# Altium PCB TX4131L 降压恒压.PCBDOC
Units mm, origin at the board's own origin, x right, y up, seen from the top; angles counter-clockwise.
Board outline 46.75 x 30.25 mm, 2 copper layers (TopLayer, BottomLayer); 29 components, 14 nets, 65 pads, 68 vias.
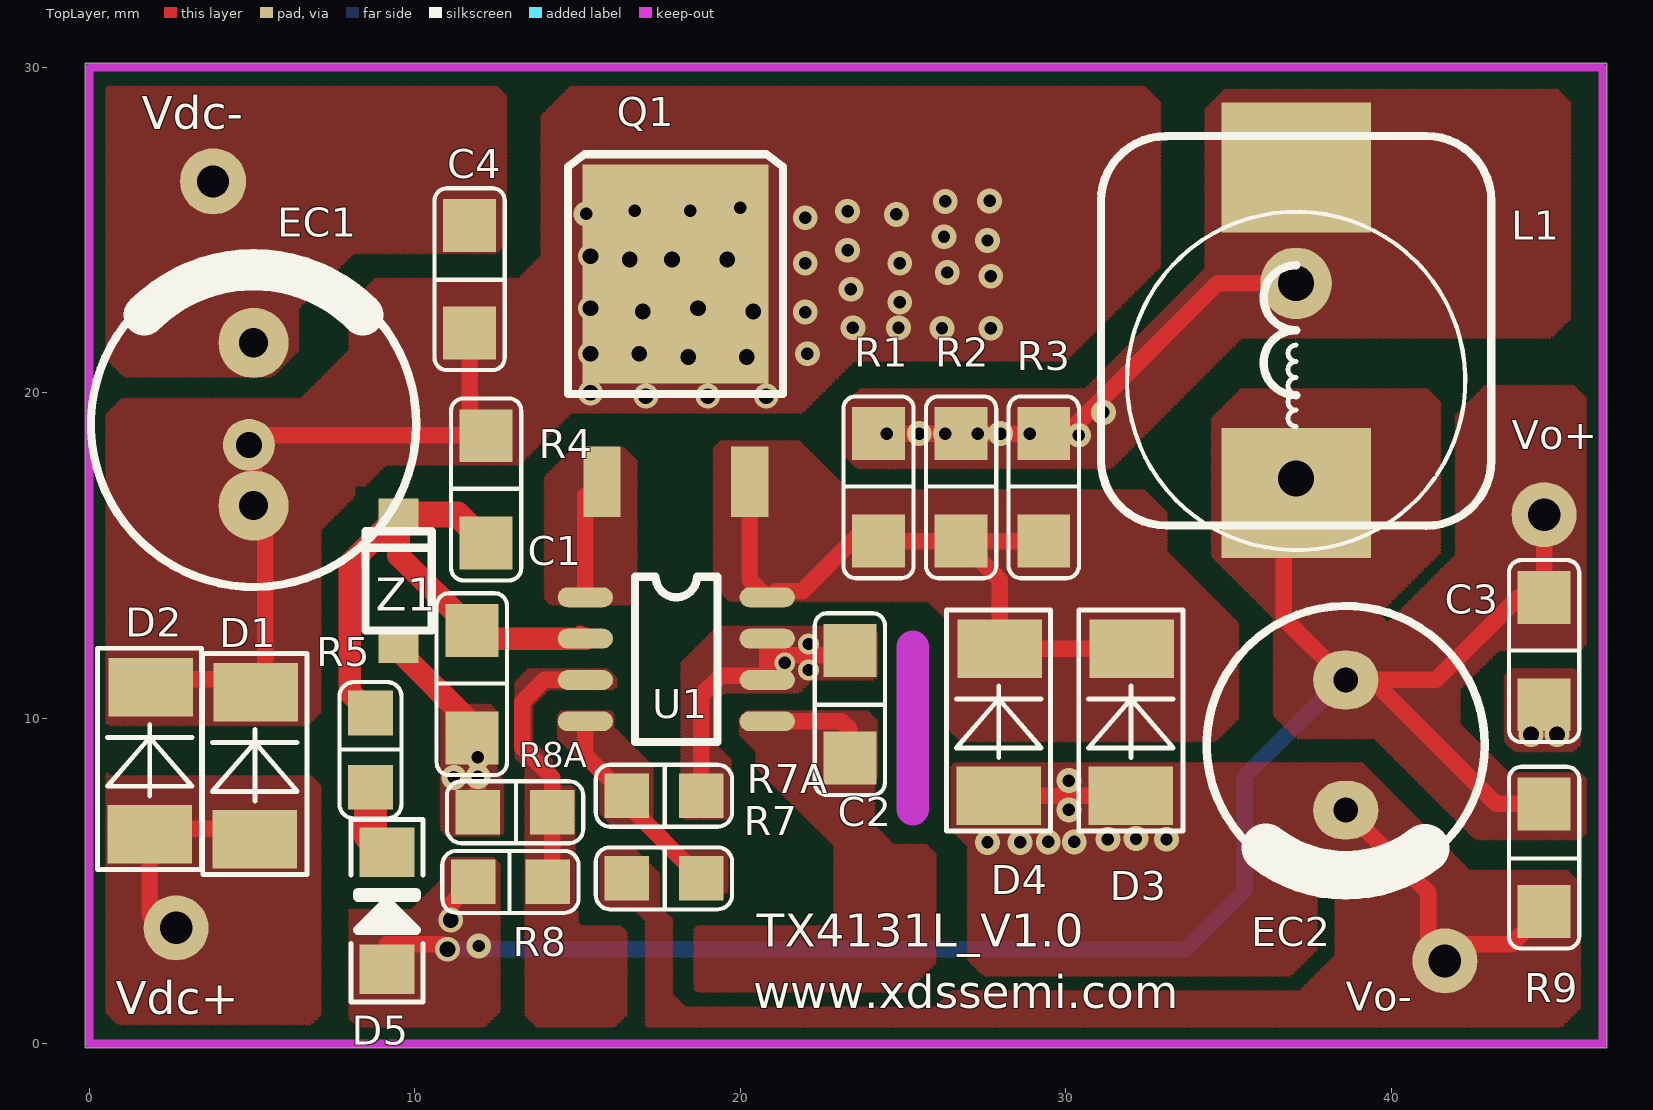
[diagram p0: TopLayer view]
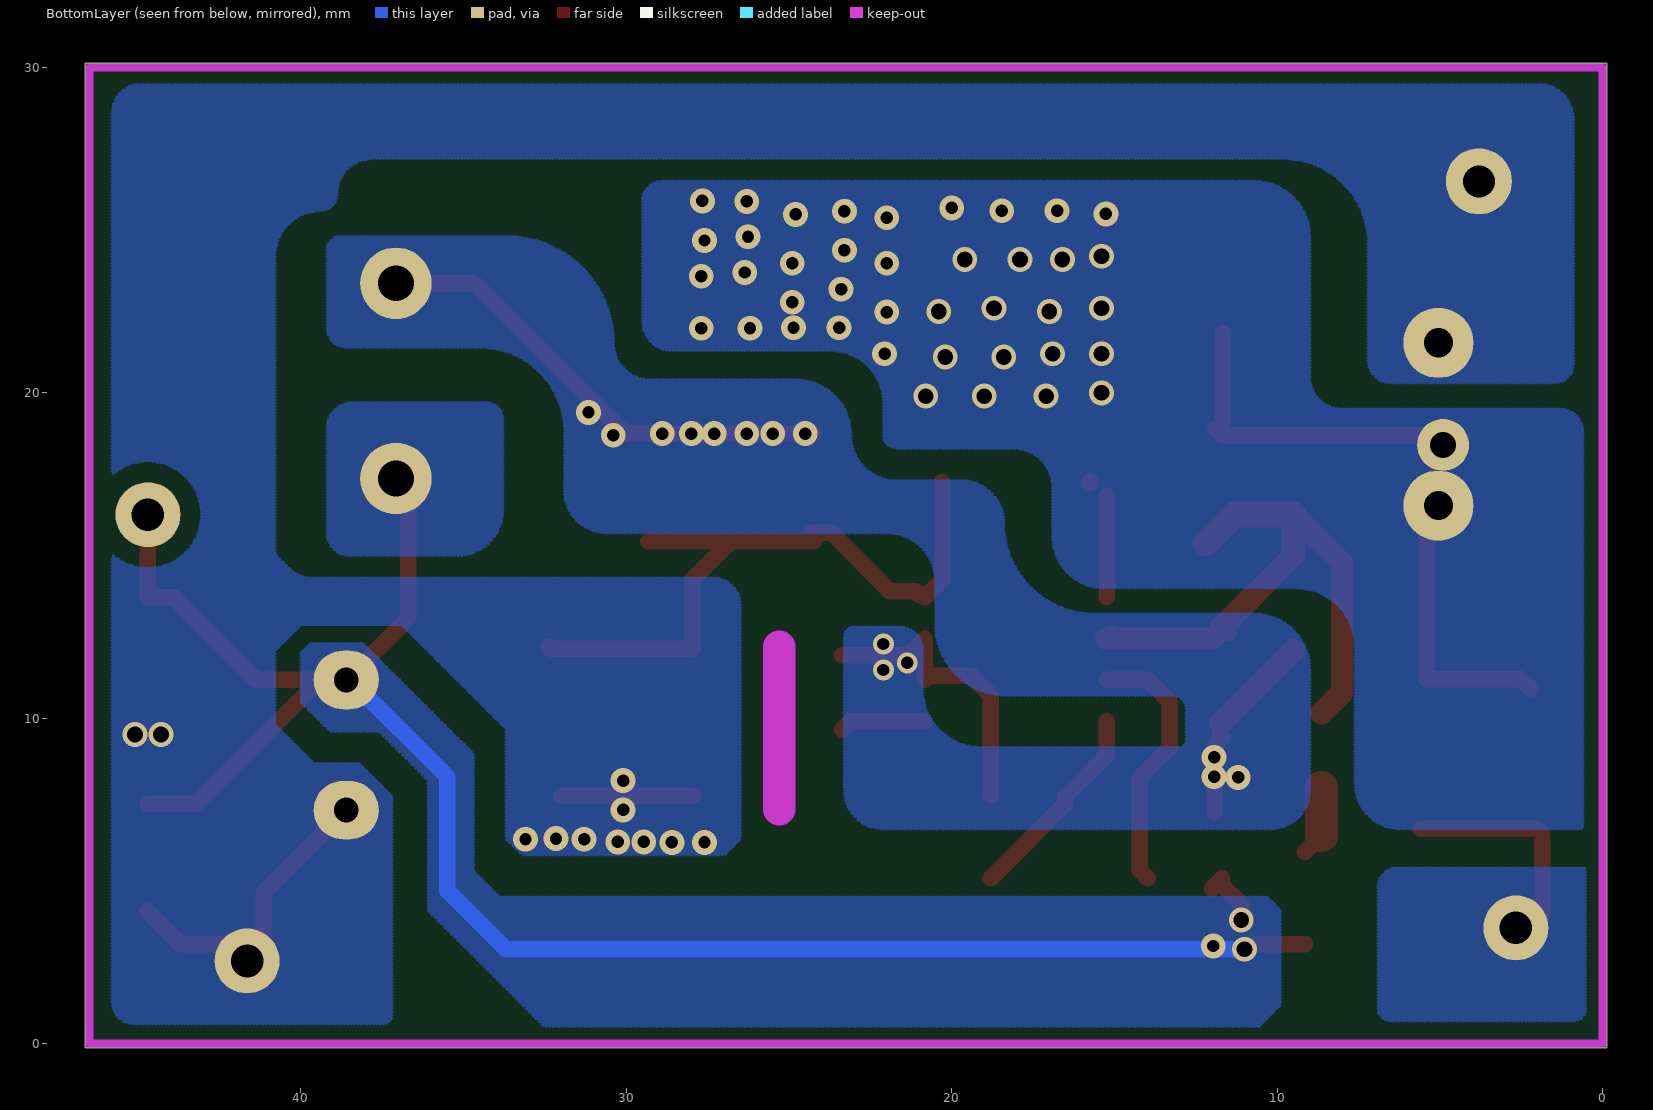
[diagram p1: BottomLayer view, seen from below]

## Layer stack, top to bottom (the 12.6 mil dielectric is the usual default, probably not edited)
TopLayer: signal copper 0.0356
Dielectric: dielectric 0.32, FR-4, Dk 4.8
BottomLayer: signal copper 0.0356

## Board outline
-0.127,-0.127 46.627,-0.127 46.627,30.127 -0.127,30.127

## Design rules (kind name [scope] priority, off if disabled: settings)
Clearance [All] p1: gap=0.35
ComponentClearance [All] p1 off: gap=0.254 collisioncheckmode=3 verticalgap=0.254 showdistances=FALSE
PolygonConnect [All] p1: connectstyle=Direct reliefconductorwidth=0.254 reliefentries=4 polygonreliefangle="90 Angle"
RoutingVias [All] p1: holewidth=0.711 width=1.27 viastyle="Through Hole" minholewidth=0.711 minwidth=1.27 maxholewidth=0.711 maxwidth=1.27
SilkscreenOverComponentPads [All] p1: minsilkscreentomaskgap=0.254
SolderMaskExpansion [All] p1: expansion=0.102
TestPointUsage [All] p1: valid=0 allowmultiple=FALSE
Testpoint [All] p1: side=15 testpointundercomponent=TRUE minsize=1.016 maxsize=2.54 preferedsize=1.524 minholesize=0.508 maxholesize=1.016 preferedholesize=0.813 testpointgrid=0.025 style=1023 order=0123456789
Width [All] p1: maxlimit=0.508 minlimit=0.508 preferedwidth=0.508
22 further rules are at their usual default settings.

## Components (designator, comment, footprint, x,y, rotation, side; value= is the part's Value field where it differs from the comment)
C1 "" R1206 11.75,12.7 r0 top
C2 "" R1206 23.368,8.783 r180 top
C3 "" R1206 44.704,13.716 r0 top
C4 "" R1206 11.684,21.844 r180 top
D1 "" SMB 5.08,6.283 r90 top
D2 "" SMB 1.848,6.44 r90 top
D3 "" SMB 32.004,7.62 r90 top
D4 "" SMB 27.94,7.62 r90 top
D5 "" DZSMA 9.144,2.283 r0 top
EC1 "" c10*16 5.044,16.536 r90 top
EC2 "" C8*12 38.608,11.176 r180 top
L1 "" L12*12 37.084,26.924 r270 top
Q1 "" TO252 15.748,17.272 r0 top
R1 "" R1206 24.248,18.748 r0 top
R2 "" R1206 26.788,18.748 r0 top
R3 "" R1206 29.328,18.748 r0 top
R4 "" R1206 12.192,18.683 r0 top
R5 "" R0805 8.636,10.16 r180 top
R7 "" r0805 18.796,5.08 r90 top
R7A "" r0805 18.796,7.62 r90 top
R8 "" r0805 11.792,4.972 r270 top
R8A "" r0805 14.224,7.112 r90 top
R9 "" R1206 44.704,4.064 r180 top
U1 "TX4131L" SOP8 15.24,13.716 r90 top
Vo+ "" pad 44.704,16.256 r0 top
Vo- "" pad 41.656,2.54 r0 top
Z1 "" SOD123 9.5,12.192 r90 top
? "" pad 2.663,3.556 r0 top
? "" L10*16 37.084,23.368 r270 top

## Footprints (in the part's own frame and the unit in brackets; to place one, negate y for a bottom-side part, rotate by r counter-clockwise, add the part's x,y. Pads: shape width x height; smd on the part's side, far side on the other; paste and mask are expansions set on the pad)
C8*12 [mm]
  oval 2x1.8 hole 0.762: 1(0,0) 2(0,4)
  silkscreen extent -4.27,-2.27 4.27,6.27
c10*16 [mil]
  round 85 hole 35.43: 1(0,0) 2(196.85,0)
  silkscreen extent -98,-197 295,197
DZSMA [mm]
  rect 1.7x1.524 smd: 1(0,0) 2(0,3.6)
  silkscreen extent -1.1,-1.01 1.1,4.6
L10*16 [mm]
  round 2.2 hole 1.1: 1(0,0) 2(6,0)
  silkscreen extent -2.2,-5.2 8.2,5.2
L12*12 [mm]
  rect 4x4.6 smd: 1(0,0) 2(10,0)
  silkscreen extent -0.97,-6 11.01,6
pad [mm]
  round 2 hole 1: 1(0,0)
R0805 [mil]
  rect 54x54 smd: 1(0,0) 2(0,90)
  silkscreen extent -38,-38 38,128
r0805 [mil]
  rect 54x54 smd: 1(0,0) 2(0,90)
  silkscreen extent -38,-38 38,128
R1206 [mil]
  rect 64x64 smd: 1(0,0) 2(0,-130)
  silkscreen extent -42,-175 42,45
SMB [mm]
  rect 1.8x2.6 smd: 1(0,0) 2(4.511,-0.031)
  silkscreen extent -1.09,-1.6 5.71,1.6
SOD123 [mm]
  rect 1x1.22 smd: 1(0,0) 2(4.064,0)
  silkscreen extent 0.51,-1.02 3.56,1.02
SOP8 [mil]
  oval 24x66.93 smd: 1(0,0) 2(-50,0) 3(-100,0) 4(-150,0) 5(-150,-220) 6(-100,-220) 7(-50,-220) 8(0,-220)
  round 27.56 on Top Overlay: ""(-22.13,-84.65)
  silkscreen extent -175,-160 25,-60
TO252 [mil]
  rect 45x85 smd: 1(0,0) 3(179,0)
  rect 225x265 smd: 2(89,251)
  silkscreen extent -41,106 219,396

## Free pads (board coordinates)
  round 2.032 hole 0.991: 0(3.8,26.5)
  round 1.6 hole 0.8: 2(4.9,18.4)

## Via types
v1: diameter 0.762, hole 0.381, TopLayer to BottomLayer, 45 vias
v2: diameter 0.762, hole 0.483, TopLayer to BottomLayer, 20 vias
v3: diameter 0.635, hole 0.381, TopLayer to BottomLayer, 3 vias

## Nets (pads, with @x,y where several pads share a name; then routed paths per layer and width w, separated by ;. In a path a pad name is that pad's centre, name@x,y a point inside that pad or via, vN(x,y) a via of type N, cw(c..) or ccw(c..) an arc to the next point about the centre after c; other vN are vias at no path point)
GND: C3.2 C4.2 D3.1 D4.1 EC1.2 EC2.2 pad.0 R7.2 R9.1 Vo-.1 | length 13.7
  TopLayer w0.508: D4.1 D3.1 ; EC2.2@38.176,7.176 EC2.2 41.148,4.636 41.148,3.048 43.688,3.048 R9.1
  other v1: 27.6,6.183 28.6,6.183 29.463,6.2 30.263,6.2 31.3,6.283 33.1,6.283 32.163,6.3 30.1,7.183 30.1,8.083
  other v2: 44.3,9.5 45.1,9.5
NetC5_1: R7.1 R7A.2 U1.4 | length 6.3
  TopLayer w0.508: U1.4 15.24,8.86 16.495,7.605 16.5,7.6 16.5,7.376 R7.1
NetD1_2: C4.1 D1.2 D2.2 EC1.1 pad.2 Q1.2 R4.1 | length 21.4
  TopLayer w0.508: D2.2@2.2,10.9 2.5,11.2 5.4,11.2 5.4,16.18 EC1.1 5.044,18.356 4.7,18.7 11.7,18.7 R4.1@11.9,18.9 ; R4.1@11.684,18.796 C4.1
  other v1: 22.063,21.2 26.2,21.983 27.7,21.983 23.463,22 24.863,22 22,22.483 24.9,22.783 23.4,23.183 27.7,23.583 26.363,23.7 22,23.983 24.9,23.983 23.3,24.383 27.6,24.683 26.263,24.8 22,25.383 24.8,25.483 15.263,25.5 23.3,25.583 16.763,25.6 18.463,25.6 20,25.683 26.3,25.883 27.663,25.9
  other v2: 17.1,19.9 19,19.9 20.8,19.9 15.4,20 18.4,21.1 20.2,21.1 15.4,21.2 16.9,21.2 17,22.5 20.4,22.5 15.4,22.6 18.7,22.6 16.6,24.1 17.9,24.1 19.6,24.1 15.4,24.2
NetD5_1: ?.2 C3.1 D5.1 EC2.1 L1.2 R8.1 R9.2 Vo+.1 | length 60.6
  TopLayer w0.508: 9.144,3.048 10.852,3.048 v2(11,2.9) ; v2(11.1,3.8) 11.1,4.279 R8.1 ; R8.1@11.684,5.08 R8.1@12,4.764 ; ?.2 36.7,16.984 36.7,13.084 EC2.1 41.376,11.176 43.916,13.716 C3.1 Vo+.1 ; EC2.1@39.424,11.176 43.234,7.366 R9.2
  BottomLayer w0.508: v2(11,2.9) 33.7,2.9 35.5,4.7 35.5,8.2 38.476,11.176 EC2.1
  other v1: 11.963,3
NetQ1_3: D3.2 D4.2 Q1.3 R1.2 R2.2 R3.2 U1.8 | length 21.2
  TopLayer w0.508: Q1.3 20.295,14.249 U1.8 ; U1.8@21,13.8 21.1,13.9 21.9,13.9 23.7,15.7 24.248,15.7 R1.2@24.3,15.7 ; R1.2 R2.2 ; R3.2 R2.2 ; D3.2@32.4,12.2 32.331,12.131 D3.2 D4.2 27.971,14.263 R2.2
NetR4A_1: C1.1 R4.2 R5.1 U1.2 Z1.2 | length 18.6
  TopLayer w0.508: C1.1@11.5,12.6 C1.1@11.6,12.7 ; C1.1@11.684,12.784 11.675,12.775 C1.1@11.6,12.7 ; C1.1 C1.1@11.75,12.75 ; C1.1@11.9,12.4 11.675,12.625 C1.1@11.6,12.7 ; U1.2@15.086,12.6 U1.2
  TopLayer w0.7: R5.1 8,10.796 8,14.756 Z1.2 9.5,15 C1.1@11.75,12.75 ; C1.1@12.054,12.446 U1.2
  TopLayer w0.8: Z1.2 11.317,16.256 R4.2
NetR5_2: D5.2 R5.2 | length 2.2
  TopLayer w0.508: D5.2@8.636,6.391 D5.2
  TopLayer w1: D5.2@8.636,6.391 R5.2
NetR6_1: 
NetR6_2: C2.1 U1.5 | length 2.6
  TopLayer w0.508: U1.5 23.114,9.906 23.368,9.652
NetR8A_1: R8.2 R8A.1 U1.3 | length 8.1
  TopLayer w0.508: R8.2@13.97,5.08 14.224,5.334 R8A.1 14.224,8.176 13.3,9.1 13.3,10.5 13.976,11.176 U1.3
NetU1_1: Q1.1 U1.1 | length 3.2
  TopLayer w0.508: U1.1 Q1.1@15.24,16.84 ; Q1.1@15.748,17.208 Q1.1
NetVAC1_1: 
NetVAC2_1: ?.1@2.663,3.556 D1.1 D2.1 | length 7.4
  TopLayer w0.508: ?.1@2.6,3.2 1.848,3.952 D2.1 2.012,6.604 D1.1@5.588,6.604
SGND: ?.1@37.084,23.368 C1.2 C2.2 L1.1 R1.1 R2.1 R3.1 R7A.1 R8A.2 U1.6 U1.7 Z1.1 | length 30.3
  TopLayer w0.508: Z1.1@9.5,12.083 Z1.1 ; C1.2@11.684,9.398 11.717,9.365 11.938,9.144 v1(11.938,8.8) v1(11.938,8.2) R8A.2 ; C1.2 C1.2@11.75,9.833 ; R7A.1 18.796,10.696 19.4,11.3 20.704,11.3 U1.6 20.828,11.7 U1.7 21.336,11.938 21.363,11.938 22.1,11.938 C2.2@23.368,11.938 ; R1.1 v1(24.5,18.748) v1(25.5,18.748) v1(26.3,18.748) R2.1 v1(27.3,18.748) v1(28,18.748) v1(28.9,18.748) R3.1 30.048,18.748 30.2,18.9 30.931,19.631 34.668,23.368 ?.1@37.084,23.368
  TopLayer w0.7: Z1.1@9.5,12.083 C1.2@11.75,9.833
  other v1: 11.2,8.183 30.4,18.7 31.163,19.4
  other v3: 22.1,11.483 21.363,11.7 22.1,12.283
pads on no net: U1.

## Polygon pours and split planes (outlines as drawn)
GND on TopLayer "TopLayer-GND" (hatched 90Degree grid 0.1 track 0.1, remove dead copper, pour order 1000): 43.5,11.2 43.5,9.3 43.8,9 45.6,9 45.8,9.2 45.8,11.3 45.6,11.5 43.7,11.5 43.5,11.3
GND on TopLayer "TopLayer-GND 1" (hatched 90Degree grid 0.1 track 0.1, remove dead copper, pour order 1001): 15.7,5.9 15.7,4.3 15.9,4.1 16.8,4.1 17.1,3.8 17.1,0.6 17.3,0.4 45.1,0.4 45.8,1.1 45.8,4.9 45.4,5.3 42.4,5.3 39,8.7 39.1,8.6 26.6,8.6 26.5,8.5 26.5,6.6 27,6.1 27,2.6 27.5,2.1 36.9,2.1 37.7,2.9 37.7,5.4 38,5.7 38.2,5.7 38.3,5.6 38.3,2.7 37.2,1.6 26.5,1.6 26,1.1 18.3,1.1 17.9,1.5 17.9,3.8 17.5,4.2 17.5,5.2 16.8,5.9 16.7,6 15.8,6
NetR8A_1 on TopLayer "TopLayer-NetR8A_1" (hatched 90Degree grid 0.1 track 0.1, remove dead copper, pour order 1002): 13.4,4.083 13.4,0.9 13.8,0.5 16.1,0.5 16.5,0.9 16.5,3.4 16.3,3.6 15.1,3.6 15,3.7 15,4 14.763,4.237 13.4,4.237
NetR8A_1 on TopLayer "TopLayer-NetR8A_1 1" (hatched 90Degree grid 0.1 track 0.1, remove dead copper, pour order 1003): 13.463,3.937
NetR8A_1 on TopLayer "TopLayer-NetR8A_1 2" (hatched 90Degree grid 0.1 track 0.1, remove dead copper, pour order 1004): 13.563,4.1
NetR6_2 on TopLayer "TopLayer-NetR6_2" (hatched 90Degree grid 0.1 track 0.1, remove dead copper, pour order 1005): 20.963,8.037 22.9,6.1 22.9,3.8 22.7,3.6 18.7,3.6 18.6,3.5 18.6,1.7 18.7,1.6 25.1,1.6 26,2.5 26,5.8 25.7,6.1 24.7,6.1 24.1,6.7 24.1,9.3 20.9,9.3 20.9,8.037
SGND on TopLayer "TopLayer-SGND" (hatched 90Degree grid 0.1 track 0.1, remove dead copper, pour order 1006): 23.7,20.1 30.6,20.1 34.3,23.8 34.3,28.7 34.9,29.3 45.1,29.3 45.5,28.9 45.5,22.3 44.9,21.7 35.4,21.7 31.4,17.7 23.6,17.7 23.2,18.1 23.2,19.6
SGND on TopLayer "TopLayer-SGND 1" (hatched 90Degree grid 0.1 track 0.1, remove dead copper, pour order 1007): 23.5,19.8
NetD5_1 on TopLayer "TopLayer-NetD5_1" (hatched 90Degree grid 0.1 track 0.1, remove dead copper, pour order 1008): 34.5,18.8 34.5,15 36.4,13.1 36.4,10.1 37.1,9.4 39.5,9.4 42.6,6.3 45.8,6.3 46,6.5 46,8.1 45.8,8.3 43.6,8.3 42.1,9.8 42.1,10.9 43.3,12.1 45.8,12.1 46,12.3 46,19.8 45.6,20.2 42.9,20.2 42,19.3 42,15 39.9,12.9 39.6,13.2 41.5,15.1 41.5,19.7 41.1,20.1 35.4,20.1 34.4,19.1 34.5,19.2
NetR6_2 on TopLayer "TopLayer-NetR6_2 1" (hatched 90Degree grid 0.1 track 0.1, remove dead copper, pour order 1009): 20.2,10.2 23.9,10.2 24.2,9.9 24.2,8.2 23.9,7.9 21.1,7.9 20.5,8.5 20.5,9 20,9.5 20,10
NetU1_1 on TopLayer "TopLayer-NetU1_1" (hatched 90Degree grid 0.1 track 0.1, remove dead copper, pour order 1010): 14,13.7 14,17.4 14.9,18.3 16.4,18.3 16.8,17.9 16.8,13.6 16.7,13.5 14.2,13.5
NetQ1_3 on TopLayer "TopLayer-NetQ1_3" (hatched 90Degree grid 0.1 track 0.1, remove dead copper, pour order 1011): 19.2,18.2 19.2,14.1 19.7,13.6 25.8,13.6 26.4,13 26.4,9.7 26.8,9.3 34.6,9.3 35.3,10 35.3,12.9 33.7,14.5 33.1,15.1 33.1,16.3 32.4,17 23.3,17 21.8,18.5 19.4,18.5 19.3,18.4 19.2,18.3
GND on TopLayer "TopLayer-GND 2" (hatched 90Degree grid 0.1 track 0.1, remove dead copper, pour order 1012): 15.6,5.7
SGND on TopLayer "TopLayer-SGND 2" (hatched 90Degree grid 0.1 track 0.1, remove dead copper, pour order 1013): 18.2,7.1 18.2,11.7 19.3,12.8 24,12.8 24.2,12.6 24.2,11.3 24.1,11.2 22.2,11.2 21.8,10.8 19.5,10.8 19.2,10.5 19.2,9.2 19.7,8.7 19.7,6.9 18.3,6.9 18.2,7
NetC5_1 on TopLayer "TopLayer-NetC5_1" (hatched 90Degree grid 0.1 track 0.1, remove dead copper, pour order 1014): 14.4,10.1 14.4,9.4 15.7,8.1 15.7,7.1 16.1,6.7 16.9,6.7 19,4.6 19.5,4.6 19.6,4.7 19.6,5.8 19.5,5.9 18.2,5.9 17.3,6.8 17.3,8.5 16.1,9.7 16.1,10.1 16,10.2 14.5,10.2
NetR8A_1 on TopLayer "TopLayer-NetR8A_1 3" (hatched 90Degree grid 0.1 track 0.1, remove dead copper, pour order 1015): 13.4,4.3 13.4,8.5 13.1,8.8 13.1,11.1 13.5,11.5 15.9,11.5 16.2,11.2 16.2,11 16.1,10.9 14.1,10.9 13.6,10.4 13.6,9.3 14.224,8.676 14.224,8.176 14.5,7.9 14.8,7.9 14.9,7.8 14.9,4 14.7,3.8 13.6,3.8 13.4,4
SGND on TopLayer "TopLayer-SGND 3" (hatched 90Degree grid 0.1 track 0.1, remove dead copper, pour order 1016): 10.8,10.2 10.8,6.6 11,6.4 12.6,6.4 12.7,6.5 12.7,8.1 12.5,8.3 12.5,10.2 12.3,10.4 10.9,10.4 10.8,10.3
NetD5_1 on TopLayer "TopLayer-NetD5_1 1" (hatched 90Degree grid 0.1 track 0.1, remove dead copper, pour order 1017): 8,4.1 9.9,4.1 10.8,5 10.8,5.6 10.9,5.7 12.4,5.7 12.6,5.5 12.6,1 12.1,0.5 8.3,0.5 8,0.8
GND on TopLayer "TopLayer-GND 3" (hatched 90Degree grid 0.1 track 0.1, remove dead copper, pour order 1018): 0.6,29.4 12.5,29.4 12.8,29.1 12.8,24.6 12.5,24.3 8.1,24.3 6.4,22.6 6.4,21.3 5.6,20.5 1.1,20.5 0.5,21.1 0.5,29.3
NetD1_2 on TopLayer "TopLayer-NetD1_2" (hatched 90Degree grid 0.1 track 0.1, remove dead copper, pour order 1019): 0.6,9.8 6.7,9.8 7.1,10.2 7.1,15.8 9.1,17.8 13.2,17.8 14.8,19.4 21.9,19.4 22.9,20.4 23.5,21 30,21 32.9,23.9 32.9,28.9 32.4,29.4 14.8,29.4 13.9,28.5 13.9,24.2 13.2,23.5 8.8,23.5 8,22.7 8,21.3 6.5,19.8 1,19.8 0.4,19.2 0.4,10
NetVAC2_1 on TopLayer "TopLayer-NetVAC2_1" (hatched 90Degree grid 0.1 track 0.1, remove dead copper, pour order 1020): 0.6,8.2 6.8,8.2 7.1,7.9 7.1,0.9 6.8,0.6 0.9,0.6 0.4,1.1 0.4,8.1 0.5,8.2
GND on BottomLayer "BottomLayer-GND" (hatched 90Degree grid 0.1 track 0.1, remove dead copper, pour order 1021): 40.263,14.5 40.963,15.2 42.6,15.2 45.663,12.137 45.663,1.283 40.1,1.283 40.1,8.3 41.483,9.683 41.483,11.8 40.8,11.8 40.8,12.083 39.8,13.083 39.8,13.983 40.263,13.983
GND on BottomLayer "BottomLayer-GND 1" (hatched 90Degree grid 0.1 track 0.1, pour order 1022): 40.8,10.883 40.8,12.083 40.183,12.7 40,12.883 36.9,12.883 33.7,9.683 33.7,6.3 33.2,5.8 27,5.8 26.5,6.3 26.5,13.5 cw(c27.3,13.5) 27.3,14.3 39.6,14.3 ccw(c39.6,15.5) 40.8,15.5 40.8,15.9 42.4,15.9 42.4,10.883
GND on BottomLayer "BottomLayer-GND 2" (hatched 90Degree grid 0.1 track 0.1, remove dead copper, pour order 1023): 40.863,10
NetD1_2 on BottomLayer "BottomLayer-NetD1_2" (hatched 90Degree grid 0.1 track 0.1, remove dead copper, pour order 1024): 0.8,6.6 6.2,6.6 ccw(c6.2,8) 7.6,8 7.6,12.2 cw(c9.4,12.2) 9.4,14 15.3,14 ccw(c15.3,15.6) 16.9,15.6 16.9,17.1 cw(c18.1,17.1) 18.1,18.3 21.7,18.3 ccw(c21.7,18.7) 22.1,18.7 22.1,19.7 cw(c23.7,19.7) 23.7,21.3 28.6,21.3 ccw(c28.6,22.2) 29.5,22.2 29.5,25.9 ccw(c28.9,25.9) 28.9,26.5 10.7,26.5 ccw(c10.7,24.8) 9,24.8 9,20.5 cw(c8,20.5) 8,19.5 1.3,19.5 ccw(c1.3,18.8) 0.6,18.8 0.6,6.7 ccw(c0.7,6.7) 0.7,6.6
NetVAC2_1 on BottomLayer "BottomLayer-NetVAC2_1" (hatched 90Degree grid 0.1 track 0.1, remove dead copper, pour order 1025): 0.6,5.4 6.3,5.4 cw(c6.3,4.8) 6.9,4.8 6.9,1.1 cw(c6.5,1.1) 6.5,0.7 0.9,0.7 cw(c0.9,1.1) 0.5,1.1 0.5,5.3 cw(c0.6,5.3) 0.6,5.4
GND on BottomLayer "BottomLayer-GND 3" (hatched 90Degree grid 0.1 track 0.1, remove dead copper, pour order 1026): 37.263,7.652 38.211,8.6 39.6,8.6 40.8,9.8 40.8,24.2 ccw(c39.4,24.2) 39.4,25.6 cw(c39.4,26.1) 38.9,26.1 ccw(c37.8,26.1) 37.8,27.2 9.8,27.2 ccw(c9.8,24.6) 7.2,24.6 7.2,21 cw(c6.5,21) 6.5,20.3 1.5,20.3 cw(c1.5,20.9) 0.9,20.9 0.9,28.4 cw(c2,28.4) 2,29.5 44.9,29.5 cw(c44.9,28.6) 45.8,28.6 45.8,1.283 cw(c45.116,1.283) 45.116,0.6 37.5,0.6 cw(c37.5,0.9) 37.2,0.9 37.2,7.583
SGND on BottomLayer "BottomLayer-SGND" (hatched 90Degree grid 0.1 track 0.1, remove dead copper, pour order 1027): 35.5,24.8 38.8,24.8 cw(c38.8,24.4) 39.2,24.4 39.2,22 cw(c38.6,22) 38.6,21.4 34.5,21.4 ccw(c34.5,18.8) 31.9,18.8 31.9,18.483 cw(c30.8,18.483) 30.8,17.383 28.463,17.383 28.463,20.4 29.263,20.4 ccw(c29.263,21.537) 30.4,21.537 cw(c33.663,21.537) 33.663,24.8
GND on BottomLayer "BottomLayer-GND 4" (hatched 90Degree grid 0.1 track 0.1, remove dead copper, pour order 1028): 37.2,7.7 37.2,1.5 38.1,0.6 45.2,0.6 45.8,1.2
NetD5_1 on BottomLayer "BottomLayer-NetD5_1" (hatched 90Degree grid 0.1 track 0.1, remove dead copper, pour order 1029): 33.8,19 33.8,16.4 ccw(c35.2,16.4) 35.2,15 38.5,15 ccw(c38.5,15.7) 39.2,15.7 39.2,18.9 ccw(c38.4,18.9) 38.4,19.7 34.3,19.7 ccw(c34.3,19.2) 33.8,19.2
SGND on BottomLayer "BottomLayer-SGND 1" (hatched 90Degree grid 0.1 track 0.1, remove dead copper, pour order 1030): 23.3,12.4 23.3,7.8 cw(c22.1,7.8) 22.1,6.6 10.2,6.6 cw(c10.2,7.8) 9,7.8 9,11.5 cw(c10.7,11.5) 10.7,13.2 15.6,13.2 ccw(c15.6,16) 18.4,16 ccw(c18.4,18.3) 20.7,18.3 cw(c18.4,18.3) 18.4,16 cw(c19.7,16) 19.7,17.3 21.7,17.3 ccw(c21.7,18.7) 23.1,18.7 cw(c24.8,18.7) 24.8,20.4 30.9,20.4 cw(c30.9,19.4) 31.9,19.4 31.9,17 cw(c30.6,17) 30.6,15.7 22,15.7 ccw(c22,14.2) 20.5,14.2 20.5,12.9 cw(c18.3,12.9) 18.3,10.7 13.2,10.7 ccw(c13.2,10.3) 12.8,10.3 12.8,9.3 ccw(c13,9.3) 13,9.1 19.1,9.1 ccw(c19.1,10.9) 20.9,10.9 20.9,12.1 cw(c21.6,12.1) 21.6,12.8 23,12.8 cw(c23,12.5) 23.3,12.5
NetD5_1 on BottomLayer "BottomLayer-NetD5_1 1" (hatched 90Degree grid 0.1 track 0.1, remove dead copper, pour order 1031): 10.7,4.5 33.9,4.5 34.7,5.3 34.7,8.9 38.1,12.3 39.7,12.3 40,12 40,10.5 39.1,9.6 37.6,9.6 36.1,8.1 36.1,4.1 34,2 32.4,0.4 10.7,0.4 9.9,1.2 9.9,4.1 10.3,4.5
NetD1_2 on TopSolder (hatched 90Degree grid 0.1 track 0.1, remove dead copper): 17.4,28.9 30.9,28.9 cw(c30.9,28) 31.8,28 31.8,23.9 cw(c30.1,23.9) 30.1,22.2 15.2,22.2 15.2,28.3 cw(c15.8,28.3) 15.8,28.9
GND on BottomSolder (hatched 90Degree grid 0.1 track 0.1, remove dead copper): 27,13.483 27,6.583 ccw(c27.6,6.583) 27.6,5.983 32.9,5.983 ccw(c32.9,6.646) 33.563,6.646 33.563,13.2 ccw(c32.763,13.2) 32.763,14 27.263,14 ccw(c27.263,13.737) 27,13.737

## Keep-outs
KeepOutLayer:
  lines w0.254: 0,0 0,30 46.5,30 46.5,0 0,0
  lines w1: 25.3,7.2 25.3,12.2

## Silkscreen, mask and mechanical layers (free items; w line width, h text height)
TopOverlay:
  text "Vdc-" at 1.6,28.1 h1.02
  text "TX4131L_V1.0" at 20.5,2.983 h1.02
  text "www.xdssemi.com" at 20.4,1.083 h1.02
  text "Vdc+" at 0.8,0.9 h1.02
TopSolder:
  rectangle: 27.4,2.2 36.8,8.4
  lines w0.508: 20.3,21.5 22.4,23.6 22.863,23.6
BottomSolder:
  lines w0.5: 20.1,24.4 29.363,24.4 ; 20.3,21.7 28.3,21.7 ; 20.3,23.1 29.3,23.083
  lines w0.508: 20.1,25.583 28.8,25.583
  lines w0.6: 14.1,20.3 14.1,24.2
